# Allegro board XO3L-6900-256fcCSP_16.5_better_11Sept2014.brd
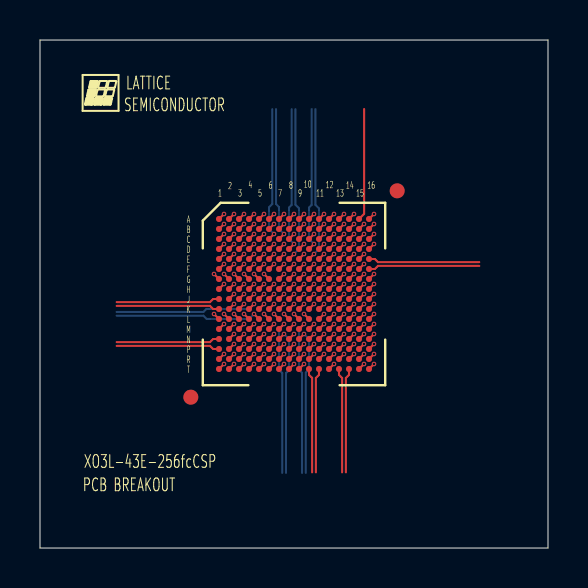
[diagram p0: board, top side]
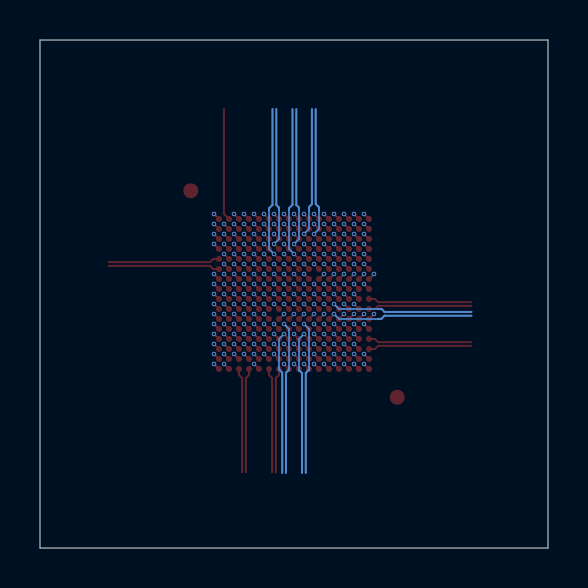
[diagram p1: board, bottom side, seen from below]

Outline 25.4 x 25.4 mm; copper layers: TOP, L2_GND, L3_SIGNAL1, L4_GND, L5_SIGNAL2, L6_PWR, L7_GND, L8_SIGNAL3, L9_GND, L10_SIGNAL4, L11_GND, BOTTOM. Coordinates in mm from the lower left corner of the outline.
Outline path: 0,25.4 25.4,25.4 25.4,0 0,0 0,25.4

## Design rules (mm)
net group CDPB4: nets PB4C PB4D
net group CDPB13: nets PB13C PB13D
net group CDPB18: nets PB18C PB18D
net group CDPB26: nets PB26C PB26D
net group CDPB31: nets PB31C PB31D
net group CDPB38: nets PB38C PB38D
net group CDPL2: nets PL2C PL2D
net group CDPL4: nets PL4C PL4D
net group CDPL6: nets PL6C PL6D
net group CDPL7: nets PL7C PL7D
net group CDPL9: nets PL9C PL9D
net group CDPL10: nets PL10C PL10D
net group CDPL15: nets PL15C PL15D
net group CDPL16: nets PL16C PL16D
net group CDPL19: nets PL19C PL19D
net group CDPL21: nets PL21C PL21D
net group CDPL23: nets PL23C PL23D
net group CDPL25: nets PL25C PL25D
net group CDPR2: nets PR2C PR2D
net group CDPR4: nets PR4C PR4D
net group CDPR6: nets PR6C PR6D
net group CDPR7: nets PR7C PR7D
net group CDPR10: nets PR10C PR10D
net group CDPR11: nets PR11C PR11D
net group CDPR16: nets PR16C PR16D
net group CDPR17: nets PR17C PR17D
net group CDPR19: nets PR19C PR19D
net group CDPR21: nets PR21C PR21D
net group CDPR23: nets PR23C PR23D
net group CDPR24: nets PR24A PR24B
net group CDPR25: nets PR25C PR25D
net group CDPT14: nets PT14C PT14D
net group CDPT17: nets PT17C PT17D
net group CDPT22: nets PT22C PT22D
net group CDPT27: nets PT27C PT27D
net group CDPT36: nets PT36C PT36D
net group PB4: nets PB4A PB4B
net group PB6: nets PB6A PB6B
net group PB7: nets PB7A PB7B
net group PB9: nets PB9A PB9B
net group PB10: nets PB10A PB10B
net group PB12: nets PB12A PB12B
net group PB13: nets PB13A PB13B
net group PB15: nets PB15A PB15B
net group PB16: nets PB16A PB16B
net group PB18: nets PB18A PB18B
net group PB21: nets PB21A PB21B
net group PB23: nets PB23A PB23B
net group PB26: nets PB26A PB26B
net group PB28: nets PB28A PB28B
net group PB29: nets PB29A PB29B
net group PB31: nets PB31A PB31B
net group PB34: nets PB34A PB34B
net group PB35: nets PB35A PB35B
net group PB37: nets PB37A PB37B
net group PB38: nets PB38A PB38B
net group PL3: nets PL3A PL3B
net group PL4: nets PL4A PL4B
net group PL6: nets PL6A PL6B
net group PL8: nets PL8A PL8B
net group PL9: nets PL9A PL9B
net group PL10: nets PL10A PL10B
net group PL11: nets PL11A PL11B
net group PL12: nets PL12A PL12B
net group PL15: nets PL15A PL15B
net group PL17: nets PL17A PL17B
net group PL19: nets PL19A PL19B
net group PL22: nets PL22A PL22B
net group PL24: nets PL24A PL24B
net group PL25: nets PL25A PL25B
net group PR2: nets PR2A PR2B
net group PR3: nets PR3A PR3B
net group PR5: nets PR5A PR5B
net group PR7: nets PR7A PR7B
net group PR9: nets PR9A PR9B
net group PR11: nets PR11A PR11B
net group PR12: nets PR12A PR12B
net group PR15: nets PR15A PR15B
net group PR16: nets PR16A PR16B
net group PR17: nets PR17A PR17B
net group PR18: nets PR18A PR18B
net group PR21: nets PR21A PR21B
net group PR23: nets PR23A PR23B
net group PT9: nets PT9A PT9B
net group PT10: nets PT10A PT10B
net group PT11: nets PT11A PT11B
net group PT12: nets PT12A PT12B
net group PT14: nets PT14A PT14B
net group PT15: nets PT15A PT15B
net group PT16: nets PT16A PT16B
net group PT17: nets PT17A PT17B
net group PT18: nets PT18A PT18B
net group PT21: nets PT21A PT21B
net group PT22: nets PT22A PT22B
net group PT25: nets PT25A PT25B
net group PT26: nets PT26A PT26B
net group PT27: nets PT27A PT27B
net group PT28: nets PT28A PT28B
net group PT32: nets PT32A PT32B
net group PT33: nets PT33A PT33B
net group PT34: nets PT34A PT34B
net group PT35: nets PT35A PT35B
net group PT36: nets PT36A PT36B

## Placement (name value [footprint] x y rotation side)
BGA  -  [BGA256C50P16X16_900X900X100B-1]  12.7 12.7 270 top
NOREF  -  []  1.85 21.54 0 top

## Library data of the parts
BGA = BGA256C50P16X16_900X900X100B-1

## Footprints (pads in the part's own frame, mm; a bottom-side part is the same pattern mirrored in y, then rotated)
BGA256C50P16X16_900X900X100B-1
  round 0.75 smd: (-5.16,5.16) (5.16,-5.16)
  round 0.305 smd: A1(-3.75,-3.75) A2(-3.75,-3.25) A3(-3.75,-2.75) A4(-3.75,-2.25) A5(-3.75,-1.75) A6(-3.75,-1.25) A7(-3.75,-0.75) A8(-3.75,-0.25) A9(-3.75,0.25) A10(-3.75,0.75) A11(-3.75,1.25) A12(-3.75,1.75) A13(-3.75,2.25) A14(-3.75,2.75) A15(-3.75,3.25) A16(-3.75,3.75) B1(-3.25,-3.75) B2(-3.25,-3.25) B3(-3.25,-2.75) B4(-3.25,-2.25) B5(-3.25,-1.75) B6(-3.25,-1.25) B7(-3.25,-0.75) B8(-3.25,-0.25) B9(-3.25,0.25) B10(-3.25,0.75) B11(-3.25,1.25) B12(-3.25,1.75) B13(-3.25,2.25) B14(-3.25,2.75) B15(-3.25,3.25) B16(-3.25,3.75) C1(-2.75,-3.75) C2(-2.75,-3.25) C3(-2.75,-2.75) C4(-2.75,-2.25) C5(-2.75,-1.75) C6(-2.75,-1.25) C7(-2.75,-0.75) C8(-2.75,-0.25) C9(-2.75,0.25) C10(-2.75,0.75) C11(-2.75,1.25) C12(-2.75,1.75) C13(-2.75,2.25) C14(-2.75,2.75) C15(-2.75,3.25) C16(-2.75,3.75) D1(-2.25,-3.75) D2(-2.25,-3.25) D3(-2.25,-2.75) D4(-2.25,-2.25) D5(-2.25,-1.75) D6(-2.25,-1.25) D7(-2.25,-0.75) D8(-2.25,-0.25) D9(-2.25,0.25) D10(-2.25,0.75) D11(-2.25,1.25) D12(-2.25,1.75) D13(-2.25,2.25) D14(-2.25,2.75) D15(-2.25,3.25) D16(-2.25,3.75) E1(-1.75,-3.75) E2(-1.75,-3.25) E3(-1.75,-2.75) E4(-1.75,-2.25) E5(-1.75,-1.75) E6(-1.75,-1.25) E7(-1.75,-0.75) E8(-1.75,-0.25) E9(-1.75,0.25) E10(-1.75,0.75) E11(-1.75,1.25) E12(-1.75,1.75) E13(-1.75,2.25) E14(-1.75,2.75) E15(-1.75,3.25) E16(-1.75,3.75) F1(-1.25,-3.75) F2(-1.25,-3.25) F3(-1.25,-2.75) F4(-1.25,-2.25) F5(-1.25,-1.75) F6(-1.25,-1.25) F7(-1.25,-0.75) F8(-1.25,-0.25) F9(-1.25,0.25) F10(-1.25,0.75) F11(-1.25,1.25) F12(-1.25,1.75) F13(-1.25,2.25) F14(-1.25,2.75) F15(-1.25,3.25) F16(-1.25,3.75) G1(-0.75,-3.75) G2(-0.75,-3.25) G3(-0.75,-2.75) G4(-0.75,-2.25) G5(-0.75,-1.75) G6(-0.75,-1.25) G7(-0.75,-0.75) G8(-0.75,-0.25) G9(-0.75,0.25) G10(-0.75,0.75) G11(-0.75,1.25) G12(-0.75,1.75) G13(-0.75,2.25) G14(-0.75,2.75) G15(-0.75,3.25) G16(-0.75,3.75) H1(-0.25,-3.75) H2(-0.25,-3.25) H3(-0.25,-2.75) H4(-0.25,-2.25) H5(-0.25,-1.75) H6(-0.25,-1.25) H7(-0.25,-0.75) H8(-0.25,-0.25) H9(-0.25,0.25) H10(-0.25,0.75) H11(-0.25,1.25) H12(-0.25,1.75) H13(-0.25,2.25) H14(-0.25,2.75) H15(-0.25,3.25) H16(-0.25,3.75) J1(0.25,-3.75) J2(0.25,-3.25) J3(0.25,-2.75) J4(0.25,-2.25) J5(0.25,-1.75) J6(0.25,-1.25) J7(0.25,-0.75) J8(0.25,-0.25) J9(0.25,0.25) J10(0.25,0.75) J11(0.25,1.25) J12(0.25,1.75) J13(0.25,2.25) J14(0.25,2.75) J15(0.25,3.25) J16(0.25,3.75) K1(0.75,-3.75) K2(0.75,-3.25) K3(0.75,-2.75) K4(0.75,-2.25) K5(0.75,-1.75) K6(0.75,-1.25) K7(0.75,-0.75) K8(0.75,-0.25) K9(0.75,0.25) K10(0.75,0.75) K11(0.75,1.25) K12(0.75,1.75) K13(0.75,2.25) K14(0.75,2.75) K15(0.75,3.25) K16(0.75,3.75) L1(1.25,-3.75) L2(1.25,-3.25) L3(1.25,-2.75) L4(1.25,-2.25) L5(1.25,-1.75) L6(1.25,-1.25) L7(1.25,-0.75) L8(1.25,-0.25) L9(1.25,0.25) L10(1.25,0.75) L11(1.25,1.25) L12(1.25,1.75) L13(1.25,2.25) L14(1.25,2.75) L15(1.25,3.25) L16(1.25,3.75) M1(1.75,-3.75) M2(1.75,-3.25) M3(1.75,-2.75) M4(1.75,-2.25) M5(1.75,-1.75) M6(1.75,-1.25) M7(1.75,-0.75) M8(1.75,-0.25) M9(1.75,0.25) M10(1.75,0.75) M11(1.75,1.25) M12(1.75,1.75) M13(1.75,2.25) M14(1.75,2.75) M15(1.75,3.25) M16(1.75,3.75) N1(2.25,-3.75) N2(2.25,-3.25) N3(2.25,-2.75) N4(2.25,-2.25) N5(2.25,-1.75) N6(2.25,-1.25) N7(2.25,-0.75) N8(2.25,-0.25) N9(2.25,0.25) N10(2.25,0.75) N11(2.25,1.25) N12(2.25,1.75) N13(2.25,2.25) N14(2.25,2.75) N15(2.25,3.25) N16(2.25,3.75) P1(2.75,-3.75) P2(2.75,-3.25) P3(2.75,-2.75) P4(2.75,-2.25) P5(2.75,-1.75) P6(2.75,-1.25) P7(2.75,-0.75) P8(2.75,-0.25) P9(2.75,0.25) P10(2.75,0.75) P11(2.75,1.25) P12(2.75,1.75) P13(2.75,2.25) P14(2.75,2.75) P15(2.75,3.25) P16(2.75,3.75) R1(3.25,-3.75) R2(3.25,-3.25) R3(3.25,-2.75) R4(3.25,-2.25) R5(3.25,-1.75) R6(3.25,-1.25) R7(3.25,-0.75) R8(3.25,-0.25) R9(3.25,0.25) R10(3.25,0.75) R11(3.25,1.25) R12(3.25,1.75) R13(3.25,2.25) R14(3.25,2.75) R15(3.25,3.25) R16(3.25,3.75) T1(3.75,-3.75) T2(3.75,-3.25) T3(3.75,-2.75) T4(3.75,-2.25) T5(3.75,-1.75) T6(3.75,-1.25) T7(3.75,-0.75) T8(3.75,-0.25) T9(3.75,0.25) T10(3.75,0.75) T11(3.75,1.25) T12(3.75,1.75) T13(3.75,2.25) T14(3.75,2.75) T15(3.75,3.25) T16(3.75,3.75)

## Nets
GND: BGA.A1 BGA.A16 BGA.F5 BGA.F10 BGA.G7 BGA.G8 BGA.G9 BGA.G10 BGA.G11 BGA.H6 BGA.H11 BGA.J6 BGA.J11 BGA.K5 BGA.K6 BGA.K7 BGA.K8 BGA.K9 BGA.K10 BGA.K11 BGA.K12 BGA.L6 BGA.T1 BGA.T16
VCC: BGA.H7 BGA.H8 BGA.H9 BGA.H10 BGA.J7 BGA.J8 BGA.J9 BGA.J10
VCCIO0: BGA.F6 BGA.F7 BGA.F8 BGA.F9
VCCIO1: BGA.G6 BGA.H5 BGA.J5
VCCIO2: BGA.L7 BGA.L8 BGA.L9 BGA.L10
VCCIO3: BGA.L11 BGA.L12
VCCIO4: BGA.H12 BGA.J12
VCCIO5: BGA.F11 BGA.G12
PB4A: BGA.P13
PB4B: BGA.R14
PB4C: BGA.N12
PB4D: BGA.M12
PB6A: BGA.T13
PB6B: BGA.T14
PB7A: BGA.P12
PB7B: BGA.R13
PB9A: BGA.M11
PB9B: BGA.N11
PB10A: BGA.R12
PB10B: BGA.P11
PB12A: BGA.T12
PB12B: BGA.R11
PB13A: BGA.N10
PB13B: BGA.M10
PB13C: BGA.P10
PB13D: BGA.R10
PB15A: BGA.T11
PB15B: BGA.T10
PB16A: BGA.T9
PB16B: BGA.R9
PB18A: BGA.N9
PB18B: BGA.M9
PB18C: BGA.P9
PB18D: BGA.P8
PB21A: BGA.R8
PB21B: BGA.T8
PB23A: BGA.T7
PB23B: BGA.R7
PB26A: BGA.N8
PB26B: BGA.M8
PB26C: BGA.T6
PB26D: BGA.R6
PB28A: BGA.P7
PB28B: BGA.P6
PB29A: BGA.T5
PB29B: BGA.R5
PB31A: BGA.N7
PB31B: BGA.M7
PB31C: BGA.T4
PB31D: BGA.R4
PB34A: BGA.R3
PB34B: BGA.T3
PB35A: BGA.M6
PB35B: BGA.N6
PB37A: BGA.R2
PB37B: BGA.T2
PB38A: BGA.M5
PB38B: BGA.N5
PB38C: BGA.P5
PB38D: BGA.P4
PL2C: BGA.D13
PL2D: BGA.C14
PL3A: BGA.B15
PL3B: BGA.B16
PL4A: BGA.C15
PL4B: BGA.C16
PL4C: BGA.D14
PL4D: BGA.E13
PL6A: BGA.D15
PL6B: BGA.D16
PL6C: BGA.F13
PL6D: BGA.F12
PL7C: BGA.E15
PL7D: BGA.E14
PL8A: BGA.G13
PL8B: BGA.G14
PL9A: BGA.F14
PL9B: BGA.F15
PL9C: BGA.E16
PL9D: BGA.F16
PL10A: BGA.G15
PL10B: BGA.G16
PL10C: BGA.H13
PL10D: BGA.H14
PL11A: BGA.H15
PL11B: BGA.H16
PL12A: BGA.J16
PL12B: BGA.J15
PL15A: BGA.K16
PL15B: BGA.K15
PL15C: BGA.J13
PL15D: BGA.J14
PL16C: BGA.L16
PL16D: BGA.K14
PL17A: BGA.M16
PL17B: BGA.L15
PL19A: BGA.N16
PL19B: BGA.M15
PL19C: BGA.K13
PL19D: BGA.L14
PL21C: BGA.M14
PL21D: BGA.L13
PL22A: BGA.P16
PL22B: BGA.N15
PL23C: BGA.P15
PL23D: BGA.R16
PL24A: BGA.R15
PL24B: BGA.T15
PL25A: BGA.M13
PL25B: BGA.N13
PL25C: BGA.N14
PL25D: BGA.P14
PR2A: BGA.A2
PR2B: BGA.B2
PR2C: BGA.D4
PR2D: BGA.E4
PR3A: BGA.B1
PR3B: BGA.C2
PR4C: BGA.D3
PR4D: BGA.C3
PR5A: BGA.D2
PR5B: BGA.C1
PR6C: BGA.F4
PR6D: BGA.G5
PR7A: BGA.D1
PR7B: BGA.E2
PR7C: BGA.F3
PR7D: BGA.E3
PR9A: BGA.G4
PR9B: BGA.G3
PR10C: BGA.E1
PR10D: BGA.F2
PR11A: BGA.G2
PR11B: BGA.F1
PR11C: BGA.H4
PR11D: BGA.H3
PR12A: BGA.H2
PR12B: BGA.G1
PR15A: BGA.H1
PR15B: BGA.J2
PR16A: BGA.J1
PR16B: BGA.K1
PR16C: BGA.J4
PR16D: BGA.J3
PR17A: BGA.K2
PR17B: BGA.L1
PR17C: BGA.L2
PR17D: BGA.K3
PR18A: BGA.M1
PR18B: BGA.M2
PR19C: BGA.K4
PR19D: BGA.L5
PR21A: BGA.N1
PR21B: BGA.P1
PR21C: BGA.L3
PR21D: BGA.L4
PR23A: BGA.M3
PR23B: BGA.N2
PR23C: BGA.R1
PR23D: BGA.P2
PR24A: BGA.N3
PR24B: BGA.M4
PR25C: BGA.P3
PR25D: BGA.N4
PT9A: BGA.A14
PT9B: BGA.B14
PT9C: BGA.A15
PT10A: BGA.E12
PT10B: BGA.E11
PT11A: BGA.A13
PT11B: BGA.B13
PT12A: BGA.C13
PT12B: BGA.D12
PT14A: BGA.E10
PT14B: BGA.D10
PT14C: BGA.D11
PT14D: BGA.C12
PT15A: BGA.B12
PT15B: BGA.A12
PT16A: BGA.A11
PT16B: BGA.B11
PT17A: BGA.B10
PT17B: BGA.A10
PT17C: BGA.C10
PT17D: BGA.C11
PT18A: BGA.B9
PT18B: BGA.A9
PT21A: BGA.E9
PT21B: BGA.D9
PT22A: BGA.C9
PT22B: BGA.C8
PT22C: BGA.A8
PT22D: BGA.B8
PT25A: BGA.D8
PT25B: BGA.E8
PT26A: BGA.B7
PT26B: BGA.A7
PT27A: BGA.D7
PT27B: BGA.E7
PT27C: BGA.C7
PT27D: BGA.C6
PT28A: BGA.A6
PT28B: BGA.B6
PT32A: BGA.A5
PT32B: BGA.B5
PT33A: BGA.D6
PT33B: BGA.C5
PT34A: BGA.E6
PT34B: BGA.E5
PT35A: BGA.A4
PT35B: BGA.B4
PT36A: BGA.A3
PT36B: BGA.B3
PT36C: BGA.C4
PT36D: BGA.D5

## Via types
v1: diameter 0.224, hole 0.127, TOP to BOTTOM, 245 vias

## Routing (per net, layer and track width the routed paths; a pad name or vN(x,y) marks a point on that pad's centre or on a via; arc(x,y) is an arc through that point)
GND: length 8.5
  TOP w0.102: BGA.J6 v1(11.7,12.7) ; BGA.K11 v1(14.2,12.2) ; BGA.G11 v1(14.2,13.7) ; BGA.H11 v1(14.2,13.2) ; BGA.J11 v1(14.2,12.7) ; BGA.K6 v1(11.7,12.2) ; BGA.K9 v1(13.2,12.2) ; BGA.G7 v1(12.2,13.7) ; BGA.K12 v1(14.7,12.2) ; BGA.G9 v1(13.2,13.7) ; BGA.T1 v1(9.2,9.2) ; BGA.F10 v1(13.7,14.2) ; BGA.T16 v1(16.7,9.2) ; BGA.K10 v1(13.7,12.2) ; BGA.A16 v1(16.7,16.7) ; BGA.L6 v1(11.2,11.7) ; BGA.G8 v1(12.7,13.7) ; BGA.H6 v1(11.7,13.2) ; BGA.K5 v1(11.2,12.2) ; BGA.K7 v1(12.2,12.2) ; BGA.G10 v1(13.7,13.7) ; BGA.K8 v1(12.7,12.2) ; BGA.A1 v1(9.2,16.7) ; BGA.F5 v1(11.2,14.2)
VCC: length 2.8
  TOP w0.102: BGA.J10 v1(13.7,12.7) ; BGA.H8 v1(12.7,13.2) ; BGA.H9 v1(13.2,13.2) ; BGA.H7 v1(12.2,13.2) ; BGA.J7 v1(12.2,12.7) ; BGA.J9 v1(13.2,12.7) ; BGA.H10 v1(13.7,13.2) ; BGA.J8 v1(12.7,12.7)
VCCIO0: length 1.4
  TOP w0.102: BGA.F9 v1(13.2,14.2) ; BGA.F8 v1(12.7,14.2) ; BGA.F6 v1(11.7,14.2) ; BGA.F7 v1(12.2,14.2)
VCCIO1: length 1.1
  TOP w0.102: BGA.G6 v1(11.2,13.7) ; BGA.J5 v1(11.2,12.7) ; BGA.H5 v1(11.2,13.2)
VCCIO2: length 1.4
  TOP w0.102: BGA.L10 v1(13.2,11.7) ; BGA.L9 v1(12.7,11.7) ; BGA.L8 v1(12.2,11.7) ; BGA.L7 v1(11.7,11.7)
VCCIO3: length 0.7
  TOP w0.102: BGA.L12 v1(14.7,11.7) ; BGA.L11 v1(14.2,11.7)
VCCIO4: length 0.7
  TOP w0.102: BGA.J12 v1(14.7,12.7) ; BGA.H12 v1(14.7,13.2)
VCCIO5: length 0.7
  TOP w0.102: BGA.G12 v1(14.7,13.7) ; BGA.F11 v1(14.2,14.2)
PB4A: length 6.9
  TOP w0.102: BGA.P13 v1(15.2,10.2)
  L3_SIGNAL1 w0.081: v1(15.2,10.2) 15.45,9.95 15.45,9.49
  L3_SIGNAL1 w0.102: 15.45,3.76 15.45,9.49
PB4B: length 6.3
  TOP w0.102: BGA.R14 v1(15.7,9.7)
  L3_SIGNAL1 w0.102: v1(15.7,9.7) 15.7,9.37 15.64,9.31 15.64,3.76
PB4C: length 7.8
  TOP w0.102: BGA.N12 v1(14.7,10.7)
  L10_SIGNAL4 w0.081: v1(14.7,10.7) 14.95,10.45 16.91,10.45
  L10_SIGNAL4 w0.102: 21.94,10.6 17.15,10.6 17,10.45 16.91,10.45
PB4D: length 7.8
  TOP w0.102: BGA.M12 v1(14.7,11.2)
  L10_SIGNAL4 w0.081: 16.91,10.95 14.95,10.95 v1(14.7,11.2)
  L10_SIGNAL4 w0.102: 21.94,10.79 17.17,10.79 17,10.95 16.91,10.95
PB6A: length 5.2
  TOP w0.102: BGA.T13 14.95,8.66 15.11,8.5 15.11,3.78
PB6B: length 5.2
  TOP w0.102: BGA.T14 15.45,8.66 15.29,8.5 15.29,3.78
PB7A: length 6.9
  TOP w0.102: BGA.P12 v1(14.7,10.2)
  L5_SIGNAL2 w0.081: 15.01,9.4 14.95,9.46 14.95,9.95 v1(14.7,10.2)
  L5_SIGNAL2 w0.102: 15.01,9.4 15.01,3.76
PB7B: length 6.3
  TOP w0.102: BGA.R13 v1(15.2,9.7)
  L5_SIGNAL2 w0.102: 15.2,3.76 v1(15.2,9.7)
PB9A: length 8
  TOP w0.102: BGA.M11 v1(14.2,11.2)
  L8_SIGNAL3 w0.081: v1(14.2,11.2) BGA.M11 13.95,9.44
  L8_SIGNAL3 w0.102: 14.09,3.76 14.09,9.15 13.95,9.29 13.95,9.44
PB9B: length 7.5
  TOP w0.102: BGA.N11 v1(14.2,10.7)
  L8_SIGNAL3 w0.081: 14.45,9.46 14.45,10.45 v1(14.2,10.7)
  L8_SIGNAL3 w0.102: 14.28,3.76 14.28,9.13 14.45,9.3 14.45,9.46
PB10A: length 6.5
  TOP w0.102: BGA.R12 v1(14.7,9.7)
  L10_SIGNAL4 w0.102: 14.8,3.76 14.8,8.66 14.98,8.84 14.98,9.42 v1(14.7,9.7)
PB10B: length 7
  TOP w0.102: BGA.P11 v1(14.2,10.2)
  L10_SIGNAL4 w0.081: 14.45,8.98 14.45,9.95 v1(14.2,10.2)
  L10_SIGNAL4 w0.102: 14.62,3.76 14.62,8.67 14.45,8.83 14.45,8.98
PB12A: length 6.3
  TOP w0.102: BGA.T12 v1(14.7,9.2)
  L3_SIGNAL1 w0.102: v1(14.7,9.2) 14.59,9.31 14.44,9.31 14.33,9.2 14.33,3.76
PB12B: length 6.4
  TOP w0.102: BGA.R11 v1(14.2,9.7)
  L3_SIGNAL1 w0.102: 14.14,3.76 14.14,9.28 14.31,9.44 14.31,9.59 v1(14.2,9.7)
PB13A: length 7.5
  TOP w0.102: BGA.N10 v1(13.7,10.7)
  L10_SIGNAL4 w0.081: 13.51,9.39 13.45,9.45 BGA.N10 v1(13.7,10.7)
  L10_SIGNAL4 w0.102: 13.6,3.76 13.6,9.31 13.51,9.39
PB13B: length 8
  TOP w0.102: BGA.M10 v1(13.7,11.2)
  L10_SIGNAL4 w0.081: 13.89,9.42 13.95,9.48 13.95,10.95 v1(13.7,11.2)
  L10_SIGNAL4 w0.102: 13.78,3.76 13.78,9.31 13.89,9.42
PB13C: length 6.9
  TOP w0.102: BGA.P10 v1(13.7,10.2)
  L5_SIGNAL2 w0.081: v1(13.7,10.2) 13.95,9.95 13.95,9.47
  L5_SIGNAL2 w0.102: 13.95,3.76 13.95,9.47
PB13D: length 6.3
  TOP w0.102: BGA.R10 v1(13.7,9.7)
  L5_SIGNAL2 w0.102: 13.76,3.76 13.76,9.31 13.7,9.37 v1(13.7,9.7)
PB15A: length 5.2
  TOP w0.102: 13.79,3.78 13.79,8.5 13.95,8.66 BGA.T11
PB15B: length 5.2
  TOP w0.102: 13.61,3.78 13.61,8.5 13.45,8.66 BGA.T10
PB16A: length 5.8
  TOP w0.102: BGA.T9 v1(13.2,9.2)
  L3_SIGNAL1 w0.102: 13.26,3.76 13.26,8.81 13.2,8.87 v1(13.2,9.2)
PB16B: length 6.4
  TOP w0.102: BGA.R9 v1(13.2,9.7)
  L3_SIGNAL1 w0.081: v1(13.2,9.7) 13.45,9.45 13.45,8.97
  L3_SIGNAL1 w0.102: 13.45,3.76 13.45,8.97
PB18A: length 7.5
  TOP w0.102: BGA.N9 v1(13.2,10.7)
  BOTTOM w0.081: v1(13.2,10.7) 13.45,10.45 13.45,9.01 13.45,9.01
  BOTTOM w0.102: 13.45,9.01 13.45,8.93 13.29,8.77 13.29,3.76
PB18B: length 8
  TOP w0.102: BGA.M9 v1(13.2,11.2)
  BOTTOM w0.081: 12.95,9.01 BGA.M9 v1(13.2,11.2)
  BOTTOM w0.102: 12.95,9.01 12.95,8.91 13.1,8.76 13.1,3.76
PB18C: length 7
  TOP w0.102: BGA.P9 v1(13.2,10.2)
  L8_SIGNAL3 w0.081: 13.45,8.96 13.45,9.95 v1(13.2,10.2)
  L8_SIGNAL3 w0.102: 13.45,8.96 13.45,8.83 13.28,8.65 13.28,3.75
PB18D: length 7
  TOP w0.102: BGA.P8 v1(12.7,10.2)
  L8_SIGNAL3 w0.081: 12.95,8.96 12.95,9.95 v1(12.7,10.2)
  L8_SIGNAL3 w0.102: 13.09,3.75 13.09,8.66 12.95,8.8 12.95,8.96
PB21A: length 6.4
  TOP w0.102: BGA.R8 v1(12.7,9.7)
  L5_SIGNAL2 w0.081: 12.95,8.97 12.95,9.45 v1(12.7,9.7)
  L5_SIGNAL2 w0.102: 12.95,3.76 12.95,8.97
PB21B: length 5.8
  TOP w0.102: BGA.T8 v1(12.7,9.2)
  L5_SIGNAL2 w0.102: v1(12.7,9.2) 12.7,8.87 12.76,8.81 12.76,3.76
PB23A: length 5.8
  TOP w0.102: BGA.T7 v1(12.2,9.2)
  L3_SIGNAL1 w0.102: v1(12.2,9.2) 12.2,8.87 12.26,8.81 12.26,3.76
PB23B: length 6.4
  TOP w0.102: BGA.R7 v1(12.2,9.7)
  L3_SIGNAL1 w0.081: 12.45,8.97 12.45,9.45 v1(12.2,9.7)
  L3_SIGNAL1 w0.102: 12.45,3.76 12.45,8.97
PB26A: length 7.5
  TOP w0.102: BGA.N8 v1(12.7,10.7)
  L10_SIGNAL4 w0.081: 12.89,8.92 12.95,8.98 12.95,10.45 v1(12.7,10.7)
  L10_SIGNAL4 w0.102: 12.89,8.92 12.8,8.83 12.8,3.76
PB26B: length 8
  TOP w0.102: BGA.M8 v1(12.7,11.2)
  L10_SIGNAL4 w0.081: 12.52,8.91 12.45,8.98 BGA.M8 v1(12.7,11.2)
  L10_SIGNAL4 w0.102: 12.52,8.91 12.61,8.82 12.61,3.76
PB26C: length 5.8
  TOP w0.102: BGA.T6 v1(11.7,9.2)
  L5_SIGNAL2 w0.102: 11.76,3.76 11.76,8.81 11.7,8.87 v1(11.7,9.2)
PB26D: length 6.4
  TOP w0.102: BGA.R6 v1(11.7,9.7)
  L5_SIGNAL2 w0.081: v1(11.7,9.7) 11.95,9.45 11.95,8.97
  L5_SIGNAL2 w0.102: 11.95,3.76 11.95,8.97
PB28A: length 7
  TOP w0.102: BGA.P7 v1(12.2,10.2)
  L8_SIGNAL3 w0.081: 12.45,8.96 12.45,9.95 v1(12.2,10.2)
  L8_SIGNAL3 w0.102: 12.45,8.96 12.45,8.83 12.28,8.65 12.28,3.75
PB28B: length 7
  TOP w0.102: BGA.P6 v1(11.7,10.2)
  L8_SIGNAL3 w0.081: 11.95,8.96 11.95,9.95 v1(11.7,10.2)
  L8_SIGNAL3 w0.102: 11.95,8.96 11.95,8.8 12.09,8.66 12.09,3.75
PB29A: length 5.8
  TOP w0.102: BGA.T5 v1(11.2,9.2)
  L3_SIGNAL1 w0.102: 11.26,3.76 11.26,8.81 11.2,8.87 v1(11.2,9.2)
PB29B: length 6.4
  TOP w0.102: BGA.R5 v1(11.2,9.7)
  L3_SIGNAL1 w0.081: v1(11.2,9.7) 11.45,9.45 11.45,8.97
  L3_SIGNAL1 w0.102: 11.45,3.76 11.45,8.97
PB31A: length 7.5
  TOP w0.102: BGA.N7 v1(12.2,10.7)
  BOTTOM w0.081: 12.45,9.01 12.45,9.01 12.45,10.45 v1(12.2,10.7)
  BOTTOM w0.102: 12.3,3.76 12.3,8.74 12.45,8.89 12.45,9.01
PB31B: length 8
  TOP w0.102: BGA.M7 v1(12.2,11.2)
  BOTTOM w0.081: v1(12.2,11.2) BGA.M7 11.95,9.01
  BOTTOM w0.102: 11.95,9.01 11.95,8.91 12.11,8.75 12.11,3.76
PB31C: length 5.8
  TOP w0.102: BGA.T4 v1(10.7,9.2)
  L5_SIGNAL2 w0.102: v1(10.7,9.2) 10.7,8.87 10.76,8.81 10.76,3.76
PB31D: length 6.4
  TOP w0.102: BGA.R4 v1(10.7,9.7)
  L5_SIGNAL2 w0.081: v1(10.7,9.7) 10.95,9.45 10.95,8.97
  L5_SIGNAL2 w0.102: 10.95,3.76 10.95,8.97
PB34A: length 6.4
  TOP w0.102: BGA.R3 v1(10.2,9.7)
  L3_SIGNAL1 w0.081: v1(10.2,9.7) 10.45,9.45 10.45,8.97
  L3_SIGNAL1 w0.102: 10.45,3.76 10.45,8.97
PB34B: length 5.8
  TOP w0.102: BGA.T3 v1(10.2,9.2)
  L3_SIGNAL1 w0.102: 10.26,3.76 10.26,8.81 10.2,8.87 v1(10.2,9.2)
PB35A: length 8
  TOP w0.102: BGA.M6 v1(11.7,11.2)
  L10_SIGNAL4 w0.081: v1(11.7,11.2) BGA.M6 11.45,8.98 11.52,8.91
  L10_SIGNAL4 w0.102: 11.6,3.76 11.6,8.83 11.52,8.91
PB35B: length 7.5
  TOP w0.102: BGA.N6 v1(11.7,10.7)
  L10_SIGNAL4 w0.081: v1(11.7,10.7) 11.95,10.45 11.95,8.98 11.89,8.92
  L10_SIGNAL4 w0.102: 11.79,3.76 11.79,8.82 11.89,8.92
PB37A: length 6.4
  TOP w0.102: BGA.R2 v1(9.7,9.7)
  L5_SIGNAL2 w0.081: v1(9.7,9.7) 9.95,9.45 9.95,8.97
  L5_SIGNAL2 w0.102: 9.95,3.76 9.95,8.97
PB37B: length 5.8
  TOP w0.102: BGA.T2 v1(9.7,9.2)
  L5_SIGNAL2 w0.102: 9.76,3.76 9.76,8.81 9.7,8.87 v1(9.7,9.2)
PB38A: length 8.4
  TOP w0.102: BGA.M5 v1(11.2,11.2)
  L10_SIGNAL4 w0.081: v1(11.2,11.2) BGA.M5 10.6,10.95 10.45,10.8 10.45,9 10.51,8.94
  L10_SIGNAL4 w0.102: 10.61,3.76 10.61,8.84 10.51,8.94
PB38B: length 7.5
  TOP w0.102: BGA.N5 v1(11.2,10.7)
  L10_SIGNAL4 w0.081: 10.89,8.94 10.95,8.99 BGA.N5 v1(11.2,10.7)
  L10_SIGNAL4 w0.102: 10.79,3.76 10.79,8.84 10.89,8.94
PB38C: length 7
  TOP w0.102: BGA.P5 v1(11.2,10.2)
  L8_SIGNAL3 w0.081: v1(11.2,10.2) 11.45,9.95 11.45,8.96
  L8_SIGNAL3 w0.102: 11.45,8.96 11.45,8.83 11.28,8.65 11.28,3.75
PB38D: length 7
  TOP w0.102: BGA.P4 v1(10.7,10.2)
  L8_SIGNAL3 w0.081: v1(10.7,10.2) 10.95,9.95 10.95,8.96
  L8_SIGNAL3 w0.102: 11.09,3.75 11.09,8.66 10.95,8.8 10.95,8.96
PL2C: length 7.3
  TOP w0.102: BGA.D13 v1(15.2,15.2)
  L8_SIGNAL3 w0.081: v1(15.2,15.2) 15.45,15.45 15.45,16.97
  L8_SIGNAL3 w0.102: 15.59,21.94 15.59,17.27 15.45,17.13 15.45,16.97
PL2D: length 6.8
  TOP w0.102: BGA.C14 v1(15.7,15.7)
  L8_SIGNAL3 w0.081: 15.95,16.99 15.95,15.95 v1(15.7,15.7)
  L8_SIGNAL3 w0.102: 15.95,16.99 15.95,17.11 15.78,17.28 15.78,21.94
PL3A: length 6.2
  TOP w0.102: BGA.B15 v1(16.2,16.2)
  L5_SIGNAL2 w0.081: 16.93,16.45 16.45,16.45 v1(16.2,16.2)
  L5_SIGNAL2 w0.102: 21.94,16.45 16.93,16.45
PL3B: length 5.6
  TOP w0.102: BGA.B16 v1(16.7,16.2)
  L5_SIGNAL2 w0.102: 21.94,16.26 17.09,16.26 17.03,16.2 v1(16.7,16.2)
PL4A: length 6.2
  TOP w0.102: BGA.C15 v1(16.2,15.7)
  L3_SIGNAL1 w0.081: 16.93,15.95 16.45,15.95 v1(16.2,15.7)
  L3_SIGNAL1 w0.102: 21.94,15.95 16.93,15.95
PL4B: length 5.6
  TOP w0.102: BGA.C16 v1(16.7,15.7)
  L3_SIGNAL1 w0.102: 21.94,15.76 17.09,15.76 17.03,15.7 v1(16.7,15.7)
PL4C: length 6.8
  TOP w0.102: BGA.D14 v1(15.7,15.2)
  L8_SIGNAL3 w0.081: 16.9,15.45 15.95,15.45 v1(15.7,15.2)
  L8_SIGNAL3 w0.102: 21.94,15.3 17.33,15.3 17.18,15.45 16.9,15.45
PL4D: length 7.3
  TOP w0.102: BGA.E13 v1(15.2,14.7)
  L8_SIGNAL3 w0.081: v1(15.2,14.7) 15.45,14.95 16.91,14.95
  L8_SIGNAL3 w0.102: 21.93,15.11 17.32,15.11 17.16,14.95 16.91,14.95
PL6A: length 6.2
  TOP w0.102: BGA.D15 v1(16.2,15.2)
  L5_SIGNAL2 w0.081: 16.93,15.45 16.45,15.45 v1(16.2,15.2)
  L5_SIGNAL2 w0.102: 21.94,15.45 16.93,15.45
PL6B: length 5.6
  TOP w0.102: BGA.D16 v1(16.7,15.2)
  L5_SIGNAL2 w0.102: 21.94,15.26 17.09,15.26 17.03,15.2 v1(16.7,15.2)
PL6C: length 7.3
  TOP w0.102: BGA.F13 v1(15.2,14.2)
  L10_SIGNAL4 w0.081: v1(15.2,14.2) 15.45,13.95 16.86,13.95
  L10_SIGNAL4 w0.102: 21.94,13.77 17.19,13.77 17.01,13.95 16.86,13.95
PL6D: length 8.2
  TOP w0.102: BGA.F12 v1(14.7,14.2)
  L10_SIGNAL4 w0.081: 16.84,13.45 15.1,13.45 14.95,13.6 14.95,13.95 v1(14.7,14.2)
  L10_SIGNAL4 w0.102: 16.84,13.45 17.03,13.45 17.17,13.58 21.94,13.58
PL7C: length 6.1
  TOP w0.102: BGA.E15 v1(16.2,14.7)
  L3_SIGNAL1 w0.102: v1(16.2,14.7) 21.94,14.7
PL7D: length 6.7
  TOP w0.102: BGA.E14 v1(15.7,14.7)
  L3_SIGNAL1 w0.081: 16.38,14.95 15.95,14.95 v1(15.7,14.7)
  L3_SIGNAL1 w0.102: 21.94,14.89 16.52,14.89 16.46,14.95 16.38,14.95
PL8A: length 7.3
  TOP w0.102: BGA.G13 v1(15.2,13.7)
  L8_SIGNAL3 w0.081: 16.96,13.45 15.45,13.45 v1(15.2,13.7)
  L8_SIGNAL3 w0.102: 21.94,13.59 17.25,13.59 17.11,13.45 16.96,13.45
PL8B: length 6.8
  TOP w0.102: BGA.G14 v1(15.7,13.7)
  L8_SIGNAL3 w0.081: v1(15.7,13.7) 15.95,13.95 16.94,13.95
  L8_SIGNAL3 w0.102: 16.94,13.95 17.11,13.95 17.28,13.78 21.94,13.78
PL9A: length 6.7
  TOP w0.102: BGA.F14 v1(15.7,14.2)
  L5_SIGNAL2 w0.081: v1(15.7,14.2) 15.95,14.45 16.43,14.45
  L5_SIGNAL2 w0.102: 21.94,14.45 16.43,14.45
PL9B: length 6.1
  TOP w0.102: BGA.F15 v1(16.2,14.2)
  L5_SIGNAL2 w0.102: 21.94,14.26 16.59,14.26 16.53,14.2 v1(16.2,14.2)
PL9C: length 5.6
  TOP w0.102: 21.96,14.29 16.9,14.29 16.74,14.45 BGA.E16
PL9D: length 5.6
  TOP w0.102: BGA.F16 16.74,13.95 16.9,14.11 21.96,14.11
PL10A: length 6.2
  TOP w0.102: BGA.G15 v1(16.2,13.7)
  L3_SIGNAL1 w0.081: 16.93,13.95 16.45,13.95 v1(16.2,13.7)
  L3_SIGNAL1 w0.102: 21.94,13.95 16.93,13.95
PL10B: length 5.6
  TOP w0.102: BGA.G16 v1(16.7,13.7)
  L3_SIGNAL1 w0.102: 21.94,13.76 17.09,13.76 17.03,13.7 v1(16.7,13.7)
PL10C: length 7.7
  TOP w0.102: BGA.H13 v1(15.2,13.2)
  L10_SIGNAL4 w0.081: v1(15.2,13.2) 15.45,12.95 15.45,12.6 15.6,12.45 16.91,12.45
  L10_SIGNAL4 w0.102: 16.91,12.45 17.07,12.45 17.21,12.59 21.95,12.59
PL10D: length 6.8
  TOP w0.102: BGA.H14 v1(15.7,13.2)
  L10_SIGNAL4 w0.081: v1(15.7,13.2) 15.95,12.95 16.94,12.95
  L10_SIGNAL4 w0.102: 16.94,12.95 17.06,12.95 17.24,12.78 21.95,12.78
PL11A: length 6.2
  TOP w0.102: BGA.H15 v1(16.2,13.2)
  L5_SIGNAL2 w0.081: 16.89,13.45 16.45,13.45 v1(16.2,13.2)
  L5_SIGNAL2 w0.102: 21.94,13.45 16.89,13.45
PL11B: length 5.6
  TOP w0.102: BGA.H16 v1(16.7,13.2)
  L5_SIGNAL2 w0.102: 21.94,13.26 17.09,13.26 17.03,13.2 v1(16.7,13.2)
PL12A: length 5.6
  TOP w0.102: BGA.J16 v1(16.7,12.7)
  L3_SIGNAL1 w0.102: 21.94,12.76 17.09,12.76 17.03,12.7 v1(16.7,12.7)
PL12B: length 6.2
  TOP w0.102: BGA.J15 v1(16.2,12.7)
  L3_SIGNAL1 w0.081: 16.93,12.95 16.45,12.95 v1(16.2,12.7)
  L3_SIGNAL1 w0.102: 21.94,12.95 16.93,12.95
PL15A: length 5.6
  TOP w0.102: BGA.K16 v1(16.7,12.2)
  L5_SIGNAL2 w0.102: 21.94,12.26 17.09,12.26 17.03,12.2 v1(16.7,12.2)
PL15B: length 6.2
  TOP w0.102: BGA.K15 v1(16.2,12.2)
  L5_SIGNAL2 w0.081: v1(16.2,12.2) 16.45,12.45 16.89,12.45
  L5_SIGNAL2 w0.102: 21.94,12.45 16.89,12.45
PL15C: length 7.3
  TOP w0.102: BGA.J13 v1(15.2,12.7)
  L8_SIGNAL3 w0.081: 16.96,12.45 15.45,12.45 v1(15.2,12.7)
  L8_SIGNAL3 w0.102: 21.94,12.59 17.25,12.59 17.11,12.45 16.96,12.45
PL15D: length 6.8
  TOP w0.102: BGA.J14 v1(15.7,12.7)
  L8_SIGNAL3 w0.081: v1(15.7,12.7) 15.95,12.95 16.94,12.95
  L8_SIGNAL3 w0.102: 16.94,12.95 17.11,12.95 17.28,12.78 21.94,12.78
PL16C: length 5.6
  TOP w0.102: BGA.L16 v1(16.7,11.7)
  L3_SIGNAL1 w0.102: v1(16.7,11.7) 17.04,11.7 17.1,11.76 21.94,11.76
PL16D: length 6.7
  TOP w0.102: BGA.K14 v1(15.7,12.2)
  L3_SIGNAL1 w0.081: 17.06,11.95 15.95,11.95 v1(15.7,12.2)
  L3_SIGNAL1 w0.102: 21.94,11.95 17.06,11.95
PL17A: length 5.6
  TOP w0.102: BGA.M16 v1(16.7,11.2)
  L5_SIGNAL2 w0.102: 21.94,11.26 17.09,11.26 17.03,11.2 v1(16.7,11.2)
PL17B: length 6.2
  TOP w0.102: BGA.L15 v1(16.2,11.7)
  L5_SIGNAL2 w0.081: 17.09,11.45 16.45,11.45 v1(16.2,11.7)
  L5_SIGNAL2 w0.102: 21.94,11.45 17.09,11.45
PL19A: length 5.6
  TOP w0.102: BGA.N16 v1(16.7,10.7)
  L3_SIGNAL1 w0.102: v1(16.7,10.7) 17.03,10.7 17.09,10.76 21.94,10.76
PL19B: length 6.2
  TOP w0.102: BGA.M15 v1(16.2,11.2)
  L3_SIGNAL1 w0.081: v1(16.2,11.2) 16.45,10.95 17.09,10.95
  L3_SIGNAL1 w0.102: 21.94,10.95 17.09,10.95
PL19C: length 7.3
  TOP w0.102: BGA.K13 v1(15.2,12.2)
  L10_SIGNAL4 w0.081: 16.94,11.95 15.45,11.95 v1(15.2,12.2)
  L10_SIGNAL4 w0.102: 21.94,11.78 17.22,11.78 17.05,11.95 16.94,11.95
PL19D: length 6.8
  TOP w0.102: BGA.L14 v1(15.7,11.7)
  L10_SIGNAL4 w0.081: 16.94,11.45 15.95,11.45 v1(15.7,11.7)
  L10_SIGNAL4 w0.102: 16.94,11.45 17.06,11.45 17.2,11.59 21.94,11.59
PL21C: length 6.8
  TOP w0.102: BGA.M14 v1(15.7,11.2)
  L8_SIGNAL3 w0.081: 16.96,11.45 15.95,11.45 v1(15.7,11.2)
  L8_SIGNAL3 w0.102: 16.96,11.45 17.14,11.45 17.3,11.61 21.94,11.61
PL21D: length 7.2
  TOP w0.102: BGA.L13 v1(15.2,11.7)
  L8_SIGNAL3 w0.081: 16.96,11.95 15.45,11.95 v1(15.2,11.7)
  L8_SIGNAL3 w0.102: 21.93,11.8 17.31,11.8 17.16,11.95 16.96,11.95
PL22A: length 5.6
  TOP w0.102: BGA.P16 v1(16.7,10.2)
  L5_SIGNAL2 w0.102: v1(16.7,10.2) 17.03,10.2 17.09,10.26 21.94,10.26
PL22B: length 6.2
  TOP w0.102: BGA.N15 v1(16.2,10.7)
  L5_SIGNAL2 w0.081: 17.09,10.45 16.45,10.45 v1(16.2,10.7)
  L5_SIGNAL2 w0.102: 21.94,10.45 17.09,10.45
PL23C: length 6.2
  TOP w0.102: BGA.P15 v1(16.2,10.2)
  L3_SIGNAL1 w0.081: v1(16.2,10.2) 16.45,9.95 16.93,9.95
  L3_SIGNAL1 w0.102: 21.95,9.95 16.93,9.95
PL23D: length 5.6
  TOP w0.102: BGA.R16 v1(16.7,9.7)
  L3_SIGNAL1 w0.102: 21.95,9.76 17.09,9.76 17.03,9.7 v1(16.7,9.7)
PL24A: length 6.4
  TOP w0.102: BGA.R15 v1(16.2,9.7)
  L5_SIGNAL2 w0.081: 16.45,8.97 16.45,9.45 v1(16.2,9.7)
  L5_SIGNAL2 w0.102: 16.45,3.76 16.45,8.97
PL24B: length 5.8
  TOP w0.102: BGA.T15 v1(16.2,9.2)
  L5_SIGNAL2 w0.102: 16.26,3.76 16.26,8.81 16.2,8.87 v1(16.2,9.2)
PL25A: length 8
  TOP w0.102: BGA.M13 v1(15.2,11.2)
  L8_SIGNAL3 w0.081: v1(15.2,11.2) BGA.M13 14.95,9.44
  L8_SIGNAL3 w0.102: 14.95,9.44 14.95,9.29 15.1,9.14 15.1,3.76
PL25B: length 7.5
  TOP w0.102: BGA.N13 v1(15.2,10.7)
  L8_SIGNAL3 w0.081: 15.45,9.46 15.45,10.45 v1(15.2,10.7)
  L8_SIGNAL3 w0.102: 15.29,3.76 15.29,9.14 15.45,9.3 15.45,9.46
PL25C: length 6.8
  TOP w0.102: BGA.N14 v1(15.7,10.7)
  L8_SIGNAL3 w0.081: 16.96,10.95 15.95,10.95 v1(15.7,10.7)
  L8_SIGNAL3 w0.102: 16.96,10.95 17.14,10.95 17.29,10.8 21.95,10.8
PL25D: length 6.8
  TOP w0.102: BGA.P14 v1(15.7,10.2)
  L8_SIGNAL3 w0.081: 16.96,10.45 15.95,10.45 v1(15.7,10.2)
  L8_SIGNAL3 w0.102: 21.95,10.61 17.3,10.61 17.14,10.45 16.96,10.45
PR2A: length 5.6
  TOP w0.102: BGA.A2 v1(9.7,16.7)
  L3_SIGNAL1 w0.102: 9.76,21.94 9.76,17.09 9.7,17.03 v1(9.7,16.7)
PR2B: length 6.2
  TOP w0.102: BGA.B2 v1(9.7,16.2)
  L3_SIGNAL1 w0.081: v1(9.7,16.2) 9.95,16.45 9.95,16.93
  L3_SIGNAL1 w0.102: 9.95,21.94 9.95,16.93
PR2C: length 7.4
  TOP w0.102: BGA.D4 v1(10.7,15.2)
  L10_SIGNAL4 w0.081: v1(10.7,15.2) 10.45,15.45 8.96,15.45
  L10_SIGNAL4 w0.102: 8.96,15.45 8.85,15.45 8.69,15.29 3.83,15.29
PR2D: length 7.4
  TOP w0.102: BGA.E4 v1(10.7,14.7)
  L10_SIGNAL4 w0.081: v1(10.7,14.7) 10.45,14.95 8.96,14.95
  L10_SIGNAL4 w0.102: 3.83,15.1 8.69,15.1 8.84,14.95 8.96,14.95
PR3A: length 5.7
  TOP w0.102: BGA.B1 v1(9.2,16.2)
  L3_SIGNAL1 w0.102: 3.83,16.14 8.81,16.14 8.87,16.2 v1(9.2,16.2)
PR3B: length 6.3
  TOP w0.102: BGA.C2 v1(9.7,15.7)
  L3_SIGNAL1 w0.081: v1(9.7,15.7) 9.45,15.95 9.02,15.95
  L3_SIGNAL1 w0.102: 3.83,15.95 9.02,15.95
PR4C: length 6.9
  TOP w0.102: BGA.D3 v1(10.2,15.2)
  L8_SIGNAL3 w0.081: v1(10.2,15.2) 9.95,15.45 8.96,15.45
  L8_SIGNAL3 w0.102: 8.96,15.45 8.81,15.45 8.65,15.61 3.86,15.61
PR4D: length 6.9
  TOP w0.102: BGA.C3 v1(10.2,15.7)
  L8_SIGNAL3 w0.081: v1(10.2,15.7) 9.95,15.95 8.96,15.95
  L8_SIGNAL3 w0.102: 8.96,15.95 8.8,15.95 8.65,15.79 3.86,15.79
PR5A: length 6.3
  TOP w0.102: BGA.D2 v1(9.7,15.2)
  L5_SIGNAL2 w0.081: v1(9.7,15.2) 9.45,15.45 9.02,15.45
  L5_SIGNAL2 w0.102: 3.83,15.45 9.02,15.45
PR5B: length 5.7
  TOP w0.102: BGA.C1 v1(9.2,15.7)
  L5_SIGNAL2 w0.102: v1(9.2,15.7) 8.87,15.7 8.81,15.64 3.83,15.64
PR6C: length 7.4
  TOP w0.102: BGA.F4 v1(10.7,14.2)
  L10_SIGNAL4 w0.081: 8.96,14.45 10.45,14.45 v1(10.7,14.2)
  L10_SIGNAL4 w0.102: 8.96,14.45 8.85,14.45 8.71,14.31 3.83,14.31
PR6D: length 7.4
  TOP w0.102: BGA.G5 v1(10.7,13.7)
  L10_SIGNAL4 w0.081: 8.96,13.95 10.45,13.95 v1(10.7,13.7)
  L10_SIGNAL4 w0.102: 3.83,14.12 8.69,14.12 8.86,13.95 8.96,13.95
PR7A: length 5.7
  TOP w0.102: BGA.D1 v1(9.2,15.2)
  L3_SIGNAL1 w0.102: v1(9.2,15.2) 8.87,15.2 8.81,15.14 3.83,15.14
PR7B: length 6.3
  TOP w0.102: BGA.E2 v1(9.7,14.7)
  L3_SIGNAL1 w0.081: 9.02,14.95 9.45,14.95 v1(9.7,14.7)
  L3_SIGNAL1 w0.102: 3.83,14.95 9.02,14.95
PR7C: length 6.9
  TOP w0.102: BGA.F3 v1(10.2,14.2)
  L8_SIGNAL3 w0.081: v1(10.2,14.2) 9.95,14.45 8.96,14.45
  L8_SIGNAL3 w0.102: 8.96,14.45 8.81,14.45 8.65,14.61 3.86,14.61
PR7D: length 6.9
  TOP w0.102: BGA.E3 v1(10.2,14.7)
  L8_SIGNAL3 w0.081: v1(10.2,14.7) 9.95,14.95 8.96,14.95
  L8_SIGNAL3 w0.102: 8.96,14.95 8.8,14.95 8.65,14.79 3.86,14.79
PR9A: length 6.9
  TOP w0.102: BGA.G4 v1(10.2,13.7)
  L8_SIGNAL3 w0.081: v1(10.2,13.7) 9.95,13.95 8.44,13.95
  L8_SIGNAL3 w0.102: 3.86,13.81 8.15,13.81 8.29,13.95 8.44,13.95
PR9B: length 6.4
  TOP w0.102: BGA.G3 v1(9.7,13.7)
  L8_SIGNAL3 w0.081: v1(9.7,13.7) 9.45,13.45 8.46,13.45
  L8_SIGNAL3 w0.102: 3.86,13.62 8.15,13.62 8.32,13.45 8.46,13.45
PR10C: length 5.7
  TOP w0.102: BGA.E1 v1(9.2,14.7)
  L5_SIGNAL2 w0.102: v1(9.2,14.7) 8.87,14.7 8.81,14.64 3.83,14.64
PR10D: length 6.3
  TOP w0.102: BGA.F2 v1(9.7,14.2)
  L5_SIGNAL2 w0.081: 9.02,14.45 9.45,14.45 v1(9.7,14.2)
  L5_SIGNAL2 w0.102: 3.83,14.45 9.02,14.45
PR11A: length 5.8
  TOP w0.102: BGA.G2 v1(9.2,13.7)
  L3_SIGNAL1 w0.081: v1(9.2,13.7) 8.95,13.95 8.52,13.95
  L3_SIGNAL1 w0.102: 3.84,13.95 8.52,13.95
PR11B: length 5.7
  TOP w0.102: BGA.F1 v1(9.2,14.2)
  L3_SIGNAL1 w0.102: 3.84,14.14 8.81,14.14 8.87,14.2 v1(9.2,14.2)
PR11C: length 7.4
  TOP w0.102: BGA.H4 v1(10.7,13.2)
  L10_SIGNAL4 w0.081: v1(10.7,13.2) 10.45,13.45 8.96,13.45
  L10_SIGNAL4 w0.102: 3.86,13.31 8.71,13.31 8.85,13.45 8.96,13.45
PR11D: length 6.9
  TOP w0.102: BGA.H3 v1(10.2,13.2)
  L10_SIGNAL4 w0.081: 8.99,12.95 BGA.H3 v1(10.2,13.2)
  L10_SIGNAL4 w0.102: 3.86,13.12 8.7,13.12 8.87,12.95 8.99,12.95
PR12A: length 6.3
  TOP w0.102: BGA.H2 v1(9.7,13.2)
  L5_SIGNAL2 w0.081: v1(9.7,13.2) 9.45,13.45 9.02,13.45
  L5_SIGNAL2 w0.102: 3.83,13.45 9.02,13.45
PR12B: length 5.2
  TOP w0.102: BGA.G1 v1(8.7,13.7)
  L5_SIGNAL2 w0.102: 3.83,13.64 8.41,13.64 8.47,13.7 v1(8.7,13.7)
PR15A: length 6.2
  TOP w0.102: BGA.H1 v1(9.2,13.2)
  L3_SIGNAL1 w0.102: v1(9.2,13.2) 9.31,13.09 9.31,12.94 9.22,12.85 3.84,12.85
PR15B: length 6.3
  TOP w0.102: BGA.J2 v1(9.7,12.7)
  L3_SIGNAL1 w0.102: v1(9.7,12.7) 9.59,12.81 9.44,12.81 9.3,12.66 3.84,12.66
PR16A: length 5.2
  TOP w0.102: 3.84,12.29 8.5,12.29 8.66,12.45 BGA.J1
PR16B: length 5.2
  TOP w0.102: 3.84,12.11 8.5,12.11 8.66,11.95 BGA.K1
PR16C: length 7.4
  TOP w0.102: BGA.J4 v1(10.7,12.7)
  L8_SIGNAL3 w0.081: v1(10.7,12.7) BGA.J4 9.53,12.45
  L8_SIGNAL3 w0.102: 3.86,12.61 9.26,12.61 9.42,12.45 9.53,12.45
PR16D: length 6.9
  TOP w0.102: BGA.J3 v1(10.2,12.7)
  L8_SIGNAL3 w0.081: v1(10.2,12.7) 9.95,12.95 9.5,12.95
  L8_SIGNAL3 w0.102: 3.86,12.8 9.27,12.8 9.42,12.95 9.5,12.95
PR17A: length 6.3
  TOP w0.102: BGA.K2 v1(9.7,12.2)
  L5_SIGNAL2 w0.102: 3.84,12.42 8.94,12.42 9.16,12.2 v1(9.7,12.2)
PR17B: length 6.1
  TOP w0.102: BGA.L1 v1(8.7,11.7)
  L5_SIGNAL2 w0.102: 3.84,12.23 8.86,12.23 8.96,12.14 8.96,11.96 v1(8.7,11.7)
PR17C: length 5.9
  TOP w0.102: BGA.L2 v1(9.2,11.7)
  L10_SIGNAL4 w0.102: 3.83,12.08 8.82,12.08 v1(9.2,11.7)
PR17D: length 6.9
  TOP w0.102: BGA.K3 v1(10.2,12.2)
  L10_SIGNAL4 w0.081: 9.48,12.45 9.95,12.45 v1(10.2,12.2)
  L10_SIGNAL4 w0.102: 9.48,12.45 9.02,12.45 8.84,12.27 3.83,12.27
PR18A: length 5.7
  TOP w0.102: BGA.M1 v1(9.2,11.2)
  L3_SIGNAL1 w0.102: v1(9.2,11.2) 8.87,11.2 8.81,11.26 3.84,11.26
PR18B: length 6.3
  TOP w0.102: BGA.M2 v1(9.7,11.2)
  L3_SIGNAL1 w0.081: 8.97,11.45 9.45,11.45 v1(9.7,11.2)
  L3_SIGNAL1 w0.102: 3.84,11.45 8.97,11.45
PR19C: length 7.4
  TOP w0.102: BGA.K4 v1(10.7,12.2)
  BOTTOM w0.081: 8.48,11.95 8.48,11.95 BGA.K4 v1(10.7,12.2)
  BOTTOM w0.102: 8.48,11.95 8.32,11.95 8.17,11.8 3.83,11.8
PR19D: length 7.4
  TOP w0.102: BGA.L5 v1(10.7,11.7)
  BOTTOM w0.081: 8.51,11.45 8.51,11.45 10.45,11.45 v1(10.7,11.7)
  BOTTOM w0.102: 3.83,11.61 8.17,11.61 8.34,11.45 8.51,11.45
PR21A: length 5.2
  TOP w0.102: 3.84,10.29 8.5,10.29 8.66,10.45 BGA.N1
PR21B: length 5.2
  TOP w0.102: BGA.P1 8.66,9.95 8.5,10.11 3.84,10.11
PR21C: length 6.4
  TOP w0.102: BGA.L3 v1(9.7,11.7)
  L8_SIGNAL3 w0.081: 8.46,11.45 9.45,11.45 v1(9.7,11.7)
  L8_SIGNAL3 w0.102: 3.86,11.62 8.14,11.62 8.31,11.45 8.46,11.45
PR21D: length 6.9
  TOP w0.102: BGA.L4 v1(10.2,11.7)
  L8_SIGNAL3 w0.081: v1(10.2,11.7) 9.95,11.95 8.44,11.95
  L8_SIGNAL3 w0.102: 3.86,11.81 8.15,11.81 8.29,11.95 8.44,11.95
PR23A: length 6.9
  TOP w0.102: BGA.M3 v1(10.2,11.2)
  L5_SIGNAL2 w0.081: 9.52,10.95 BGA.M3 v1(10.2,11.2)
  L5_SIGNAL2 w0.102: 9.52,10.95 9.42,10.95 9.36,10.89 3.83,10.89
PR23B: length 6.2
  TOP w0.102: BGA.N2 v1(9.7,10.7)
  L5_SIGNAL2 w0.102: v1(9.7,10.7) 3.83,10.7
PR23C: length 6.2
  TOP w0.102: BGA.R1 v1(9.2,9.7)
  L3_SIGNAL1 w0.102: 3.84,10.07 9.19,10.07 9.31,9.96 9.31,9.81 v1(9.2,9.7)
PR23D: length 6.3
  TOP w0.102: BGA.P2 v1(9.7,10.2)
  L3_SIGNAL1 w0.102: v1(9.7,10.2) 9.6,10.1 9.44,10.1 9.27,10.26 3.84,10.26
PR24A: length 6.9
  TOP w0.102: BGA.N3 v1(10.2,10.7)
  L8_SIGNAL3 w0.081: 9.42,10.49 9.46,10.45 BGA.N3 v1(10.2,10.7)
  L8_SIGNAL3 w0.102: 9.42,10.49 9.3,10.6 3.86,10.6
PR24B: length 7.4
  TOP w0.102: BGA.M4 v1(10.7,11.2)
  L8_SIGNAL3 w0.081: 9.44,10.92 9.48,10.95 BGA.M4 v1(10.7,11.2)
  L8_SIGNAL3 w0.102: 3.86,10.79 9.32,10.79 9.44,10.92
PR25C: length 7
  TOP w0.102: BGA.P3 v1(10.2,10.2)
  L8_SIGNAL3 w0.081: v1(10.2,10.2) BGA.P3 9.95,8.96
  L8_SIGNAL3 w0.102: 10.11,3.75 10.11,8.67 9.95,8.83 9.95,8.96
PR25D: length 7.5
  TOP w0.102: BGA.N4 v1(10.7,10.7)
  L8_SIGNAL3 w0.081: v1(10.7,10.7) BGA.N4 10.45,8.94
  L8_SIGNAL3 w0.102: 10.3,3.76 10.3,8.67 10.45,8.82 10.45,8.94
PT9A: length 5.6
  TOP w0.102: BGA.A14 v1(15.7,16.7)
  L3_SIGNAL1 w0.102: 15.76,21.94 15.76,17.09 15.7,17.03 v1(15.7,16.7)
PT9B: length 6.2
  TOP w0.102: BGA.B14 v1(15.7,16.2)
  L3_SIGNAL1 w0.081: v1(15.7,16.2) 15.95,16.45 15.95,16.93
  L3_SIGNAL1 w0.102: 15.95,21.94 15.95,16.93
PT9C: length 5.6
  TOP w0.102: 16.21,21.95 16.21,16.71 BGA.A15
PT10A: length 7.8
  TOP w0.102: BGA.E12 v1(14.7,14.7)
  L10_SIGNAL4 w0.081: 16.53,14.52 16.46,14.45 14.95,14.45 v1(14.7,14.7)
  L10_SIGNAL4 w0.102: 21.94,14.6 16.61,14.6 16.53,14.52
PT10B: length 8.3
  TOP w0.102: BGA.E11 v1(14.2,14.7)
  L10_SIGNAL4 w0.081: 16.53,14.86 16.44,14.95 14.45,14.95 v1(14.2,14.7)
  L10_SIGNAL4 w0.102: 21.94,14.79 16.6,14.79 16.53,14.86
PT11A: length 5.6
  TOP w0.102: BGA.A13 v1(15.2,16.7)
  L5_SIGNAL2 w0.102: v1(15.2,16.7) 15.2,17.03 15.26,17.09 15.26,21.95
PT11B: length 6.2
  TOP w0.102: BGA.B13 v1(15.2,16.2)
  L5_SIGNAL2 w0.081: 15.45,16.93 15.45,16.45 v1(15.2,16.2)
  L5_SIGNAL2 w0.102: 15.45,21.95 15.45,16.93
PT12A: length 7.3
  TOP w0.102: BGA.C13 v1(15.2,15.7)
  L10_SIGNAL4 w0.081: 16.93,15.95 15.45,15.95 v1(15.2,15.7)
  L10_SIGNAL4 w0.102: 21.94,15.78 17.23,15.78 17.06,15.95 16.93,15.95
PT12B: length 7.8
  TOP w0.102: BGA.D12 v1(14.7,15.2)
  L10_SIGNAL4 w0.081: v1(14.7,15.2) 14.95,15.45 16.94,15.45
  L10_SIGNAL4 w0.102: 21.94,15.59 17.19,15.59 17.05,15.45 16.94,15.45
PT14A: length 7.8
  TOP w0.102: BGA.E10 v1(13.7,14.7)
  BOTTOM w0.081: 13.95,16.89 13.95,14.95 v1(13.7,14.7)
  BOTTOM w0.102: 13.77,21.95 13.77,17.16 13.95,16.98 13.95,16.89
PT14B: length 7.3
  TOP w0.102: BGA.D10 v1(13.7,15.2)
  BOTTOM w0.081: 13.45,16.89 13.45,16.89 13.45,15.45 v1(13.7,15.2)
  BOTTOM w0.102: 13.58,21.95 13.58,17.16 13.45,17.02 13.45,16.89
PT14C: length 7.3
  TOP w0.102: BGA.D11 v1(14.2,15.2)
  L8_SIGNAL3 w0.081: v1(14.2,15.2) 14.45,15.45 14.45,16.97
  L8_SIGNAL3 w0.102: 14.45,16.97 14.45,17.13 14.59,17.27 14.59,21.94
PT14D: length 6.8
  TOP w0.102: BGA.C12 v1(14.7,15.7)
  L8_SIGNAL3 w0.081: v1(14.7,15.7) 14.95,15.95 14.95,16.99
  L8_SIGNAL3 w0.102: 14.78,21.94 14.78,17.28 14.95,17.11 14.95,16.99
PT15A: length 6.2
  TOP w0.102: BGA.B12 v1(14.7,16.2)
  L3_SIGNAL1 w0.081: v1(14.7,16.2) 14.95,16.45 14.95,16.93
  L3_SIGNAL1 w0.102: 14.95,21.94 14.95,16.93
PT15B: length 5.6
  TOP w0.102: BGA.A12 v1(14.7,16.7)
  L3_SIGNAL1 w0.102: v1(14.7,16.7) 14.7,17.03 14.76,17.09 14.76,21.94
PT16A: length 5.6
  TOP w0.102: BGA.A11 v1(14.2,16.7)
  L5_SIGNAL2 w0.102: v1(14.2,16.7) 14.2,17.03 14.26,17.09 14.26,21.94
PT16B: length 6.2
  TOP w0.102: BGA.B11 v1(14.2,16.2)
  L5_SIGNAL2 w0.081: 14.45,16.93 14.45,16.45 v1(14.2,16.2)
  L5_SIGNAL2 w0.102: 14.45,21.94 14.45,16.93
PT17A: length 6.2
  TOP w0.102: BGA.B10 v1(13.7,16.2)
  L3_SIGNAL1 w0.081: 13.95,16.94 13.95,16.45 v1(13.7,16.2)
  L3_SIGNAL1 w0.102: 13.95,21.94 13.95,16.94
PT17B: length 5.6
  TOP w0.102: BGA.A10 v1(13.7,16.7)
  L3_SIGNAL1 w0.102: v1(13.7,16.7) 13.7,17.03 13.76,17.09 13.76,21.94
PT17C: length 6.8
  TOP w0.102: BGA.C10 v1(13.7,15.7)
  L8_SIGNAL3 w0.081: 13.45,16.99 13.45,15.95 v1(13.7,15.7)
  L8_SIGNAL3 w0.102: 13.45,16.99 13.45,17.11 13.61,17.27 13.61,21.94
PT17D: length 6.8
  TOP w0.102: BGA.C11 v1(14.2,15.7)
  L8_SIGNAL3 w0.081: 13.95,16.99 13.95,15.95 v1(14.2,15.7)
  L8_SIGNAL3 w0.102: 13.8,21.94 13.8,17.26 13.95,17.11 13.95,16.99
PT18A: length 6.2
  TOP w0.102: BGA.B9 v1(13.2,16.2)
  L5_SIGNAL2 w0.081: v1(13.2,16.2) 13.45,16.45 13.45,16.93
  L5_SIGNAL2 w0.102: 13.45,21.94 13.45,16.93
PT18B: length 5.6
  TOP w0.102: BGA.A9 v1(13.2,16.7)
  L5_SIGNAL2 w0.102: 13.26,21.94 13.26,17.09 13.2,17.03 v1(13.2,16.7)
PT21A: length 7.8
  TOP w0.102: BGA.E9 v1(13.2,14.7)
  L10_SIGNAL4 w0.081: v1(13.2,14.7) 12.95,14.95 12.95,16.94
  L10_SIGNAL4 w0.102: 12.95,16.94 12.95,17.07 13.1,17.22 13.1,21.94
PT21B: length 7.3
  TOP w0.102: BGA.D9 v1(13.2,15.2)
  L10_SIGNAL4 w0.081: v1(13.2,15.2) 13.45,15.45 13.45,16.93
  L10_SIGNAL4 w0.102: 13.45,16.93 13.45,17.06 13.29,17.22 13.29,21.94
PT22A: length 6.8
  TOP w0.102: BGA.C9 v1(13.2,15.7)
  L8_SIGNAL3 w0.081: v1(13.2,15.7) 12.95,15.95 12.95,16.99
  L8_SIGNAL3 w0.102: 12.8,21.94 12.8,17.26 12.95,17.11 12.95,16.99
PT22B: length 6.8
  TOP w0.102: BGA.C8 v1(12.7,15.7)
  L8_SIGNAL3 w0.081: v1(12.7,15.7) 12.45,15.95 12.45,16.99
  L8_SIGNAL3 w0.102: 12.45,16.99 12.45,17.11 12.61,17.27 12.61,21.94
PT22C: length 5.6
  TOP w0.102: BGA.A8 v1(12.7,16.7)
  L3_SIGNAL1 w0.102: v1(12.7,16.7) 12.7,17.03 12.76,17.09 12.76,21.94
PT22D: length 6.2
  TOP w0.102: BGA.B8 v1(12.7,16.2)
  L3_SIGNAL1 w0.081: 12.95,16.93 12.95,16.45 v1(12.7,16.2)
  L3_SIGNAL1 w0.102: 12.95,21.94 12.95,16.93
PT25A: length 7.3
  TOP w0.102: BGA.D8 v1(12.7,15.2)
  BOTTOM w0.081: v1(12.7,15.2) 12.45,15.45 12.45,16.89 12.45,16.89
  BOTTOM w0.102: 12.45,16.89 12.45,17.02 12.58,17.16 12.58,21.94
PT25B: length 7.8
  TOP w0.102: BGA.E8 v1(12.7,14.7)
  BOTTOM w0.081: 12.95,16.89 12.95,14.95 v1(12.7,14.7)
  BOTTOM w0.102: 12.77,21.94 12.77,17.17 12.95,16.99 12.95,16.89
PT26A: length 6.2
  TOP w0.102: BGA.B7 v1(12.2,16.2)
  L5_SIGNAL2 w0.081: v1(12.2,16.2) 12.45,16.45 12.45,16.94
  L5_SIGNAL2 w0.102: 12.45,21.94 12.45,16.94
PT26B: length 5.6
  TOP w0.102: BGA.A7 v1(12.2,16.7)
  L5_SIGNAL2 w0.102: v1(12.2,16.7) 12.2,17.03 12.26,17.09 12.26,21.94
PT27A: length 7.3
  TOP w0.102: BGA.D7 v1(12.2,15.2)
  L10_SIGNAL4 w0.081: v1(12.2,15.2) 12.45,15.45 12.45,16.93
  L10_SIGNAL4 w0.102: 12.45,16.93 12.45,17.06 12.29,17.22 12.29,21.94
PT27B: length 7.8
  TOP w0.102: BGA.E7 v1(12.2,14.7)
  L10_SIGNAL4 w0.081: v1(12.2,14.7) 11.95,14.95 11.95,16.94
  L10_SIGNAL4 w0.102: 12.1,21.94 12.1,17.22 11.95,17.07 11.95,16.94
PT27C: length 6.8
  TOP w0.102: BGA.C7 v1(12.2,15.7)
  BOTTOM w0.081: 11.95,16.88 11.95,15.95 v1(12.2,15.7)
  BOTTOM w0.102: 11.8,21.94 11.8,17.2 11.95,17.05 11.95,16.88
PT27D: length 6.8
  TOP w0.102: BGA.C6 v1(11.7,15.7)
  BOTTOM w0.081: v1(11.7,15.7) 11.45,15.95 11.45,16.85
  BOTTOM w0.102: 11.61,21.94 11.61,17.2 11.45,17.04 11.45,16.85
PT28A: length 5.6
  TOP w0.102: BGA.A6 v1(11.7,16.7)
  L3_SIGNAL1 w0.102: 11.76,21.94 11.76,17.09 11.7,17.03 v1(11.7,16.7)
PT28B: length 6.2
  TOP w0.102: BGA.B6 v1(11.7,16.2)
  L3_SIGNAL1 w0.081: 11.95,16.93 11.95,16.45 v1(11.7,16.2)
  L3_SIGNAL1 w0.102: 11.95,21.94 11.95,16.93
PT32A: length 5.6
  TOP w0.102: BGA.A5 v1(11.2,16.7)
  L5_SIGNAL2 w0.102: v1(11.2,16.7) 11.2,17.03 11.26,17.09 11.26,21.94
PT32B: length 6.2
  TOP w0.102: BGA.B5 v1(11.2,16.2)
  L5_SIGNAL2 w0.081: 11.45,16.93 11.45,16.45 v1(11.2,16.2)
  L5_SIGNAL2 w0.102: 11.45,21.94 11.45,16.93
PT33A: length 7.3
  TOP w0.102: BGA.D6 v1(11.7,15.2)
  L8_SIGNAL3 w0.081: v1(11.7,15.2) 11.95,15.45 11.95,16.97
  L8_SIGNAL3 w0.102: 11.95,16.97 11.95,17.12 11.79,17.28 11.79,21.94
PT33B: length 6.8
  TOP w0.102: BGA.C5 v1(11.2,15.7)
  L8_SIGNAL3 w0.081: 11.45,16.99 11.45,15.95 v1(11.2,15.7)
  L8_SIGNAL3 w0.102: 11.45,16.99 11.45,17.11 11.6,17.27 11.6,21.94
PT34A: length 7.8
  TOP w0.102: BGA.E6 v1(11.7,14.7)
  L10_SIGNAL4 w0.081: 11.45,16.94 11.45,14.95 v1(11.7,14.7)
  L10_SIGNAL4 w0.102: 11.45,16.94 11.45,17.07 11.3,17.22 11.3,21.94
PT34B: length 7.8
  TOP w0.102: BGA.E5 v1(11.2,14.7)
  L10_SIGNAL4 w0.081: 10.95,16.94 10.95,14.95 v1(11.2,14.7)
  L10_SIGNAL4 w0.102: 11.11,21.94 11.11,17.23 10.95,17.07 10.95,16.94
PT35A: length 5.6
  TOP w0.102: BGA.A4 v1(10.7,16.7)
  L3_SIGNAL1 w0.102: v1(10.7,16.7) 10.7,17.03 10.76,17.09 10.76,21.94
PT35B: length 6.2
  TOP w0.102: BGA.B4 v1(10.7,16.2)
  L3_SIGNAL1 w0.081: v1(10.7,16.2) 10.95,16.45 10.95,16.93
  L3_SIGNAL1 w0.102: 10.95,21.94 10.95,16.93
PT36A: length 5.6
  TOP w0.102: BGA.A3 v1(10.2,16.7)
  L5_SIGNAL2 w0.102: 10.26,21.94 10.26,17.09 10.2,17.03 v1(10.2,16.7)
PT36B: length 6.2
  TOP w0.102: BGA.B3 v1(10.2,16.2)
  L5_SIGNAL2 w0.081: 10.45,16.93 10.45,16.45 v1(10.2,16.2)
  L5_SIGNAL2 w0.102: 10.45,21.94 10.45,16.93
PT36C: length 6.8
  TOP w0.102: BGA.C4 v1(10.7,15.7)
  L8_SIGNAL3 w0.081: v1(10.7,15.7) 10.45,15.95 10.45,16.99
  L8_SIGNAL3 w0.102: 10.61,21.94 10.61,17.27 10.45,17.11 10.45,16.99
PT36D: length 7.3
  TOP w0.102: BGA.D5 v1(11.2,15.2)
  L8_SIGNAL3 w0.081: v1(11.2,15.2) 10.95,15.45 10.95,16.97
  L8_SIGNAL3 w0.102: 10.95,16.97 10.95,17.13 10.8,17.28 10.8,21.94

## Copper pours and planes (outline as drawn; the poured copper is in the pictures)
GND on L2_GND: 3.53,3.45 3.53,21.74 11.38,21.74 11.38,13.89 13.51,13.89 13.51,21.74 21.77,21.74 21.74,3.45
VCC on L6_PWR: 3.53,16.97 3.53,21.74 13.39,21.74 13.39,14.27 14.07,13.59 14.07,11.99 11.53,11.99 11.53,14.02 9.3,14.02 6.35,16.97
VCCIO0 on L2_GND: 11.51,14 11.51,21.74 13.39,21.74 13.39,14
VCCIO1 on L6_PWR: 11.4,13.89 11.4,11.99 8.25,8.84 3.53,8.84 3.53,16.84 6.25,16.84 9.19,13.89
VCCIO2 on L6_PWR: 3.53,3.45 3.53,8.71 8.31,8.71 11.46,11.86 13.64,11.86 13.64,3.45
VCCIO3 on L6_PWR: 13.79,3.45 13.79,11.86 15.65,11.86 19.25,8.25 21.74,8.25 21.74,5.46 21.74,3.45
VCCIO4 on L6_PWR: 14.2,11.99 14.2,13.39 15.47,13.39 17.86,15.77 21.74,15.77 21.74,8.38 19.33,8.38 15.72,11.99
VCCIO5 on L6_PWR: 14.33,13.51 13.51,14.33 13.51,21.74 21.74,21.74 21.74,15.93 17.81,15.93 15.39,13.51

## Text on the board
User.Comments: REN | RP | 09/03/14 | DWG NO: | XO3L-43E-256FCCSP | REVISION | 1.0 | SHEET | 1 | OF | LATTICE SEMICONDUCTOR CORPORATION | XO3L-43E-256FCCSP PCB BREAKOUT
Ref Des/Silkscreen Top: A | B | C | D | E | F | G | H | J | K | L | M | N | P | R | T | 1 | 2 | 3 | 4 | 5 | 6 | 7 | 8 | 9 | 10 | 11 | 12 | 13 | 14 | 15 | 16 | PCB BREAKOUT | XO3L-43E-256fcCSP | SEMICONDUCTOR | LATTICE
PAGE_OUTLINE: SPECIAL INSTRUCTIONS: | 1/2 OZ CU FOR EXTERNAL AND INTERNAL LAYERS | VIA IN PADS ARE TO BE NON CONDUCTIVE EXPOXY FILLED | GND     PLANE  (L2) | SIGNAL1        (L3) | TOP SIDE       (L1) | GND     PLANE  (L4) | SIGNAL2        (L5) | POWER   PLANE  (L6) | TOP SOLDERMASK | GND     PLANE  (L9) | TOP SILKSCREEN | GND     PLANE  (L7) | SIGNAL4        (L10) | GND     PLANE  (L11) | SIGNAL3        (L8) | BOTTOM SIDE    (L12) | BOTTOM SILKSCREEN | BOTTOM SOLDERMASK | DESIGNED BY: | APPROVED BY: | SIGNATURES         DATE | REV | 1 | INITIAL RELEASE | TRACE WIDTH/SPACE | ESCAPE VIA DRILL | ESCAPE VIA PAD | LAND OPENING | PACKAGE SIZE | LAND PAD | PITCH | DESCRIPTION | 0.102/0.086 | 0.2235 | 0.3048 | 0.127 | 9 x 9 | 0.50 | MM | MM/DD/YYYY | DATE | 354.3x354.3 | 4.00/3.40 | 19.69 | 8.80 | 12.00 | 5.00 | MILS | APPEOVED | X. XXXXX | 12 LAYER STACKUP | PCB BREAKOUT DETAILS | REVISION
User.5: FIGURE | SIZE | 5.0 | DRILL CHART: TOP to BOTTOM | ALL UNITS ARE IN MILS | PLATED | QTY | 245
